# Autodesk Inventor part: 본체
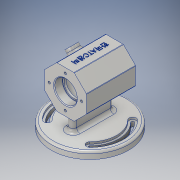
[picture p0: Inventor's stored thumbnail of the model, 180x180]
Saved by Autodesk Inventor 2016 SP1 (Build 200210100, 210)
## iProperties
Created: 2017-06
Part Number: 본체
Material: 알루미늄 6061
Document SubType Name: Modeling
Designer: basic
Density: 2.7 g/cm^3
Appearance: 알루미늄 - 평지
Mass: 560.449 g
Surface Area: 565.555 cm^2
Volume: 207.574 cm^3
Author: basic
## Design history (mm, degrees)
sketch "스케치1"
  geometry: C1 r 55 at (0, 0); 1 further point
  constraints: 1 centre point, 1 coincident
  dimensions: "d0" = 110 diameter of C1
extrude "돌출1" new body sketch "스케치1" distance "d1" = 10; taper "d2" = 0 deg
sketch "스케치2"
  geometry: A1 r 43 centre (0, 0) between (-30.406, 30.406) and (-30.406, -30.406); A2 r 48 centre (0, 0) between (-33.941, 33.941) and (-33.941, -33.941); A3 r 38 centre (0, 0) between (-26.87, 26.87) and (-26.87, -26.87); A4 r 5 centre (-30.406, 30.406) between (-26.87, 26.87) and (-33.941, 33.941); A5 r 5 centre (-30.406, -30.406) between (-33.941, -33.941) and (-26.87, -26.87); 2 further points
  constraints: 11 point on circle, 5 centre point, 4 tangent, 1 coincident, 1 horizontal alignment
  dimensions: "d3" = 48 radius of A2; "d4" = 38 radius of A3; "d10" = 90 deg dimension on point (0, 0) A1.start A1.end; "d79" = 43 radius of A1 (derived)
extrude "돌출2" cut sketch "스케치2" distance "d15" = 3; taper "d16" = 0 deg
sketch "스케치3"
  geometry: C1 r 55 at (0, 0) reference; A1 r 5 centre (-30.406, -30.406) between (-33.941, -33.941) and (-26.87, -26.87) reference; A2 r 38 centre (0, 0) between (-26.87, 26.87) and (-26.87, -26.87) reference; A3 r 5 centre (-30.406, 30.406) between (-26.87, 26.87) and (-33.941, 33.941) reference; A4 r 48 centre (0, 0) between (-33.941, 33.941) and (-33.941, -33.941) reference; A5 r 2 centre (-30.406, -30.406) between (-31.82, -31.82) and (-28.991, -28.991); A6 r 41 centre (0, 0) between (-28.991, 28.991) and (-28.991, -28.991); A7 r 2 centre (-30.406, 30.406) between (-28.991, 28.991) and (-31.82, 31.82); A8 r 45 centre (0, 0) between (-31.82, 31.82) and (-31.82, -31.82); 1 further point
  constraints: 8 point on circle, 4 centre point, 3 other
  dimensions: "d17" = 2 radius of A5
extrude "돌출3" cut sketch "스케치3" stored distance "d18" = 3; taper "d19" = 0 deg
sketch "스케치4"
  geometry: L1 (-38, 7)-(-38, 10) reference; L2 (-38, 10)-(38, 10) reference; L3 (38, 10)-(38, 7) reference; L4 (38, 7)-(41, 7) reference; L5 (41, 7)-(41, 0) reference; L6 (41, 0)-(-41, 0) reference; L7 (-41, 0)-(-41, 7) reference; L8 (-41, 7)-(-38, 7) reference; L9 (55, 10)-(55, 0) reference; L10 (55, 0)-(45, 0) reference; L11 (45, 0)-(45, 7) reference; L12 (45, 7)-(48, 7) reference; L13 (48, 7)-(48, 10) reference; L14 (48, 10)-(55, 10) reference; L15 (-55, 0)-(-55, 10) reference; L16 (-55, 10)-(-48, 10) reference; L17 (-48, 10)-(-48, 7) reference; L18 (-48, 7)-(-45, 7) reference; L19 (-45, 7)-(-45, 0) reference; L20 (-45, 0)-(-55, 0) reference; L21 (0, 0)-(0, 92); L22 (0, 0)-(0, 62); L23 (30, 49.574)-(12.426, 32); L24 (12.426, 32)-(-12.426, 32); L25 (-12.426, 32)-(-30, 49.574); L26 (-30, 49.574)-(-30, 74.426); L27 (-30, 74.426)-(-12.426, 92); L28 (-12.426, 92)-(12.426, 92); L29 (12.426, 92)-(30, 74.426); L30 (30, 74.426)-(30, 49.574); 1 further point
  constraints: 20 end point, 1 coincident, 1 parallel, 1 point on line, 1 vertical, 17 other
  dimensions: "d20" = 92 distance of L21.start L21.end; "d21" = 62 distance of L21.start L22.end; "d24" = 92 distance between parallel lines of L6 L28
extrude "돌출4" join sketch "스케치4" stored distance "d25" = 70; taper "d26" = 0 deg
sketch "스케치5"
  geometry: L1 (0, 55)-(10, 55) reference; L2 (10, 55)-(10, -55) reference; L3 (10, -55)-(0, -55) reference; L4 (0, -55)-(0, 55) reference; L5 (92, -35)-(32, -35) reference; L6 (32, -35)-(32, 35) reference; L7 (32, 35)-(92, 35) reference; L8 (92, 35)-(92, -35) reference; L9 (92, 35)-(74.426, 35) reference; L10 (78, 35)-(78, 23); L11 (78, 23)-(76, 23); L12 (74.426, 35)-(74.426, -35) reference; L13 (76, 23)-(76, 20); L14 (76, 20)-(87, 20); L15 (87, 20)-(87, -20); L16 (87, -20)-(76, -20); L17 (76, -20)-(76, -23); L18 (76, -23)-(78, -23); L19 (78, -23)-(78, -35); L20 (74.426, -35)-(92, -35) reference; L21 (62, 35)-(62, -35); L22 (78, 35)-(62, 35); L23 (78, -35)-(62, -35); L24 (49.574, -35)-(74.426, -35) reference; 1 further point
  constraints: 24 end point, 10 perpendicular, 3 collinear, 2 midpoint, 2 point on line
  dimensions: "d32" = 40 distance between parallel lines of L16 L14; "d33" = 12 distance between parallel lines of L20 L18; "d34" = 12 distance between parallel lines of L11 L7; "d35" = 3 distance between parallel lines of L14 L11; "d36" = 62 distance between parallel lines of L4 L21; "d37" = 16 distance between parallel lines of L21 L10; "d38" = 14 distance between parallel lines of L21 L13; "d39" = 25 distance between parallel lines of L21 L15
revolve "회전1" sketch "스케치5" stored, may be unused: angle "d40" = 90 deg
sketch "스케치6"
  geometry: L1 (0, -24)-(0, 24); L2 (5, -24)-(5, 24); L3 (-5, 24)-(-5, -24); A1 r 5 centre (0, -24) between (-5, -24) and (5, -24); A2 r 5 centre (0, 24) between (5, 24) and (-5, 24); 1 further point
  constraints: 8 end point, 4 point on circle, 4 tangent, 2 centre point, 1 midpoint, 1 parallel, 1 vertical
  dimensions: "d41" = 48 distance of L1.end L1.start; "d42" = 5 radius of A1
extrude "돌출5" join sketch "스케치6" stored distance "d43" = 70; taper "d44" = 0 deg
fillet "모깎기1" dims "d45" = 5
fillet "모깎기2" dims "d46" = 5
chamfer "모따기1" distance "d47" = 1; stored, may be unused: second distance "d48" = 2, angle "d49" = 45 deg
fillet "모깎기3" dims "d50" = 3
sketch "스케치7"
  geometry: L1 (12.426, 32)-(-12.426, 32) reference; L2 (-12.426, 32)-(-30, 49.574) reference; L3 (-30, 49.574)-(-30, 74.426) reference; L4 (-30, 74.426)-(-12.426, 92) reference; L5 (-12.426, 92)-(12.426, 92) reference; L6 (12.426, 92)-(30, 74.426) reference; L7 (30, 74.426)-(30, 49.574) reference; L8 (30, 49.574)-(12.426, 32) reference; L9 (32.378, 10)-(42.426, 10) reference; L10 (42.426, 10)-(42.426, 0) reference; L11 (42.426, 0)-(-42.426, 0) reference; L12 (-42.426, 0)-(-42.426, 10) reference; L13 (-42.426, 10)-(-32.378, 10) reference; L14 (-32.378, 10)-(-32.378, 7) reference; L15 (-32.378, 7)-(-28.433, 7) reference; L16 (-28.433, 7)-(-28.433, 10) reference; L17 (-28.433, 10)-(28.433, 10) reference; L18 (28.433, 10)-(28.433, 7) reference; L19 (28.433, 7)-(32.378, 7) reference; L20 (32.378, 7)-(32.378, 10) reference; L21 (0, 62)-(0, 85); C1 r 17 at (0, 62) reference; 2 further points
  constraints: 2 end point, 1 coincident, 1 vertical
  dimensions: "d51" = 23 distance of L21.start L21.end
hole "구멍1" sketch "스케치7" at (0, 85) diameter "d52" = 3.242; stored, may be unused: countersink angle "d56" = 90 deg, drill point angle "d58" = 118 deg; dims "d53" = 8, "d54" = 4, "d55" = 2, "d57" = 10
fillet "모깎기4" dims "d62" = 0.3
fillet "모깎기5" dims "d63" = 3
sketch "스케치8"
  geometry: L1 (45, 0)-(45, 7) reference; L2 (45, 7)-(48, 7) reference; L3 (48, 7)-(48, 10) reference; L4 (48, 10)-(52, 10) reference; L5 (55, 7)-(55, 0) reference; L6 (55, 0)-(45, 0) reference; L7 (-45, 7)-(-45, 0) reference; L8 (-45, 0)-(-55, 0) reference; L9 (-55, 0)-(-55, 7) reference; L10 (-52, 10)-(-48, 10) reference; L11 (-48, 10)-(-48, 7) reference; L12 (-48, 7)-(-45, 7) reference; L13 (-41, 0)-(-41, 7) reference; L14 (-41, 7)-(-38, 7) reference; L15 (-38, 7)-(-38, 10) reference; L16 (-38, 10)-(-10, 10) reference; L17 (-5, 15)-(-5, 27) reference; L18 (-10, 32)-(-12.426, 32) reference; L19 (-12.426, 32)-(-30, 49.574) reference; L20 (-30, 49.574)-(-30, 74.426) reference; L21 (-30, 74.426)-(-12.426, 92) reference; L22 (-12.426, 92)-(12.426, 92) reference; L23 (12.426, 92)-(30, 74.426) reference; L24 (30, 74.426)-(30, 49.574) reference; L25 (30, 49.574)-(12.426, 32) reference; L26 (12.426, 32)-(10, 32) reference; L27 (5, 27)-(5, 15) reference; L28 (10, 10)-(38, 10) reference; L29 (38, 10)-(38, 7) reference; L30 (38, 7)-(41, 7) reference; L31 (41, 7)-(41, 0) reference; L32 (41, 0)-(-41, 0) reference; L33 (-26.163, 88.163)-(-20.506, 93.82); L34 (-20.506, 93.82)-(-12.021, 85.335); L35 (-30, 74.426)-(-12.426, 92) reference; L36 (-12.021, 85.335)-(-17.678, 79.678); L37 (-17.678, 79.678)-(-26.163, 88.163); L38 (-17.678, 79.678)-(0, 62); C1 r 25 at (0, 62) reference; A1 r 3 centre (52, 7) between (55, 7) and (52, 10) reference; A2 r 3 centre (-52, 7) between (-52, 10) and (-55, 7) reference; A3 r 5 centre (-10, 15) between (-10, 10) and (-5, 15) reference; A4 r 5 centre (-10, 27) between (-5, 27) and (-10, 32) reference; A5 r 5 centre (10, 27) between (10, 32) and (5, 27) reference; A6 r 5 centre (10, 15) between (5, 15) and (10, 10) reference; 1 further point
  constraints: 10 end point, 4 perpendicular, 1 collinear, 1 tangent
  dimensions: "d65" = 8 distance of L33.start L33.end; "d66" = 7 distance between parallel lines of L21 L33
revolve "회전2" sketch "스케치8" stored, may be unused: angle "d67" = 90 deg
sketch "스케치9"
  geometry: C1 r 8 at (0, 0) reference; C2 r 4 at (0, 0); 1 further point
  constraints: 1 centre point, 1 coincident
  dimensions: "d68" = 8 diameter of C2
extrude "돌출6" cut sketch "스케치9" stored distance "d69" = 70; taper "d70" = 0 deg
chamfer "모따기2" distance "d71" = 1; stored, may be unused: second distance "d72" = 2, angle "d73" = 45 deg
fillet "모깎기6" dims "d74" = 1
sketch "스케치10"
  geometry: L1 (0, 70)-(24.024, 70) reference; L2 (42.012, 0)-(42.012, 70) reference; 2 further points
  constraints: 1 other
  dimensions: "d75" = 35 distance from line of point (12.012, 35) L1; "d76" = 30 distance from line of L2 point (12.012, 35)
feature "엠보싱1" sketch "스케치10" dims "d17" = 2, "d77" = 0.5, "d78" = 0
fillet "모깎기7" dims "d80" = 3
node "솔리드1"
mirror "대칭1"
pattern_circular "원형 패턴1" dims angle "d60" = 360 deg
mirror "대칭2"
node "절단 모서리 투영1"
node "절단 모서리 투영2"
node "절단 모서리 투영3"
node "절단 모서리 투영4"
node "절단 모서리 투영5"
node "절단 모서리 투영6"
